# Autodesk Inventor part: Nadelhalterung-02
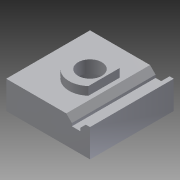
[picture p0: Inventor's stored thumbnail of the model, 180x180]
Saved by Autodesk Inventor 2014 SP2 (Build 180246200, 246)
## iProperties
Company: VDW-Nachwuchsstiftung
Created: 2014-04
Part Number: Nadelhalterung-02
Material: Aluminium 6061
Document SubType Name: Modeling
Designer: e_dammj
Density: 2.71 g/cm^3
Appearance: Aluminium - flach
Project: Verstellbarer Werkstückanschlag
Mass: 24.5784 g
Surface Area: 36.3222 cm^2
Volume: 9.06953 cm^3
Author: e_dammj
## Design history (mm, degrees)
sketch "Skizze1"
  geometry: L1 (-15, 15)-(15, 15); L2 (15, 15)-(15, -15); L3 (15, -15)-(-15, -15); L4 (-15, -15)-(-15, 15); L5 (-15, 15)-(15, -15); L6 (15, 15)-(-15, -15); 1 further point
  constraints: 12 end point, 2 midpoint, 2 parallel, 1 horizontal, 1 perpendicular
  dimensions: "d0" = 30 distance of L2.end L3.end; "d1" = 30 distance of L1.end L2.end
extrude "Grundkörper" new body sketch "Skizze1" distance "d2" = 10; taper "d3" = 0 deg
sketch "Skizze2"
  geometry: C1 r 7.5 at (0, 0); 1 further point
  constraints: 1 centre point, 1 coincident
  dimensions: "d4" = 15 diameter of C1
extrude "Ansatz D=15" join sketch "Skizze2" distance "d5" = 3; taper "d6" = 0 deg
sketch "Skizze3"
  geometry: 2 further points
  constraints: 1 coincident
hole "Senkbohrung" sketch "Skizze3" at (0, 0) diameter "d7" = 8.5; stored, may be unused: countersink angle "d11" = 90 deg, drill point angle "d13" = 118 deg; dims "d8" = 6, "d9" = 13.5, "d10" = 8.5, "d12" = 8
sketch "Skizze4"
  geometry: L1 (30, 0)-(0, 0) reference; L2 (0, 0)-(0, 10) reference; L3 (28.5, 0)-(26.5, 2); L4 (26.5, 2)-(26.5, 3); L5 (25, 4.983)-(25, -1.414); L6 (26.5, 3)-(25, 3); L7 (15, -2.352)-(15, 14.525); L8 (21.5, 0)-(23.5, 2); L9 (23.5, 2)-(23.5, 3); L10 (23.5, 3)-(25, 3); L11 (25, 0)-(28.5, 0); L12 (25, 0)-(21.5, 0); L13 (30, 0)-(30, 10) reference; L14 (-0.651, 5)-(31.282, 5); L15 (21.5, 10)-(23.5, 8); L16 (23.5, 8)-(23.5, 7); L17 (25, 10)-(21.5, 10); L18 (23.5, 7)-(25, 7); L19 (26.5, 8)-(26.5, 7); L20 (26.5, 7)-(25, 7); L21 (28.5, 10)-(26.5, 8); L22 (25, 10)-(28.5, 10); L23 (22.5, 13)-(7.5, 13) reference; L24 (22.5, 13)-(7.5, 13) reference; L25 (7.5, 10)-(22.5, 10) reference; L26 (7.5, 10)-(7.5, 13) reference; L27 (22.5, 10)-(22.5, 13) reference; L28 (22.5, 10)-(20, 10); L29 (20, 10)-(20, 13); L30 (20, 13)-(22.5, 13); L31 (22.5, 13)-(22.5, 10); 4 further points
  constraints: 46 end point, 12 symmetric about line, 7 point on line, 4 perpendicular, 3 parallel, 2 collinear, 2 midpoint, 1 horizontal
  dimensions: "d15" = 3 diameter of L4 L5; "d16" = 10 distance between parallel lines of L7 L5; "d17" = 1 distance from line of L3.end L6; "d18" = 3 distance from line of L6 L3.start; "d19" = 45 deg angle of L5 L3; "d24" = 12.5 distance between parallel lines of L26 L29
  node "Projizierte Kontur1"
extrude "Nut Unterteil" cut sketch "Skizze4" stored distance "d20" = 1.5; taper "d21" = 0 deg
extrude "Nut Oberteil" cut sketch "Skizze4" stored distance "d22" = 1.5; taper "d23" = 0 deg
node "Volumenkörper1"
